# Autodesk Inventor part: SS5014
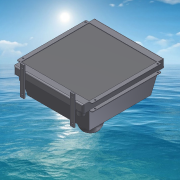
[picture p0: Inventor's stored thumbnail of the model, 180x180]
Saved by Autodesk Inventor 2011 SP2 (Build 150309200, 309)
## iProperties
Created: 2014-12
Part Number: SS5014
Document SubType Name: Modeling
Designer: Дорохин
Density: 0.416315 g/cm^3
Mass: 30000 g
Surface Area: 15790.2 cm^2
Volume: 72060.8 cm^3
Author: Дорохин
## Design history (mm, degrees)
sketch "Эскиз1"
  geometry: L1 (-275, 325)-(275, 325); L2 (300, 270)-(300, -270); L3 (275, -325)-(-275, -325); L4 (-300, -270)-(-300, 270); L5 (-295, 275)-(-275, 275); L6 (-275, 275)-(-275, 325); L7 (275, 325)-(275, 275); L8 (275, 275)-(295, 275); L9 (-295, -275)-(-275, -275); L10 (-275, -275)-(-275, -325); L11 (275, -325)-(275, -275); L12 (275, -275)-(295, -275); L13 (-295, 275)-(-300, 270); L14 (-300, -270)-(-295, -275); L15 (295, -275)-(300, -270); L16 (300, 270)-(295, 275); 5 further points
  constraints: 32 end point, 8 point on line, 6 perpendicular, 5 parallel, 1 horizontal
  dimensions: "d2" = 325 distance from line of point (0, 0) L1 (= 0.5 x d3); "d3" = 650 distance between parallel lines of L1 L3; "d4" = 0 distance between parallel lines of L5 L8; "d5" = 0 distance between parallel lines of L10 L6; "d6" = 0 distance between parallel lines of L12 L9; "d7" = 0 distance between parallel lines of L11 L7; "d8" = 25 distance between parallel lines of L6 L4 (= d10); "d9" = 550 distance between parallel lines of L7 L6; "d10" = 25 distance between parallel lines of L2 L7 (derived); "d11" = 50 distance between parallel lines of L8 L1 (= d13); "d12" = 550 distance between parallel lines of L12 L8; "d13" = 50 distance between parallel lines of L3 L12 (derived); "d14" = 300 distance from line of point (0, 0) L4 (= 0.5 x d15); "d15" = 600 distance between parallel lines of L2 L4; "d20" = 5 distance of L5.start point (-300, 275); "d21" = 5 distance of L4.end point (-300, 275) (= d20); "d22" = 5 distance of L4.start point (-300, -275) (= d20); "d23" = 5 distance of L9.start point (-300, -275) (= d22); "d24" = 5 distance of L12.end point (300, -275) (= d20); "d25" = 5 distance of L2.end point (300, -275) (= d24); "d26" = 5 distance of L2.start point (300, 275) (= d20); "d27" = 5 distance of L8.end point (300, 275) (= d26)
extrude "Выдавливание1" new body sketch "Эскиз1" distance "d28" = 63; taper "d29" = 0 deg
sketch "Эскиз2"
  geometry: L1 (-295, 275)-(-275, 275) reference; L2 (-300, -270)-(-300, 270) reference; L3 (-275, -275)-(-295, -275) reference; L4 (-289.5, 263.5)-(-285.5, 263.5); L5 (-285.5, 254.5)-(-289.5, 254.5); A1 r 4.5 centre (-289.5, 259) between (-289.5, 263.5) and (-289.5, 254.5); A2 r 4.5 centre (-285.5, 259) between (-285.5, 254.5) and (-285.5, 263.5); 1 further point
  constraints: 4 end point, 4 point on circle, 3 tangent, 2 centre point, 1 parallel
  dimensions: "d30" = 9 diameter of A1; "d31" = 9 diameter of A2; "d32" = 0 vertical distance of A2.centre A1.centre; "d33" = 4 distance of A2.centre A1.centre; "d34" = 16 distance from line of A2.centre L1; "d35" = 10.5 distance from line of A1.centre L2
extrude "Выдавливание2" cut sketch "Эскиз2" distance "d36" = 63; taper "d37" = 0 deg
pattern_linear "Прямоуг.массив1" dims "d40" = -498, "d43" = 575
sketch "Эскиз3"
  geometry: L1 (20, 63)-(0, 63) reference; L2 (0, 0)-(20, 0) reference; L3 (20, 0)-(20, 63) reference; L4 (20, 4)-(-5, 4); L5 (-5, 0)-(-5, 63) reference; L6 (-5, 4)-(-5, 59); L7 (-5, 59)-(20, 59); L8 (20, 0)-(20, 63) reference; L9 (20, 4)-(20, 59); L10 (570, 0)-(570, 63) reference; L11 (570, 4)-(595, 4); L12 (595, 0)-(595, 63) reference; L13 (595, 4)-(595, 59); L14 (595, 59)-(570, 59); L15 (570, 59)-(570, 4); L16 (570, 0)-(590, 0) reference; L17 (590, 63)-(570, 63) reference; 1 further point
  constraints: 16 end point, 8 point on line, 5 perpendicular, 1 collinear
  dimensions: "d44" = 4 distance between parallel lines of L4 L2; "d45" = 4 distance between parallel lines of L1 L7 (= d44); "d46" = 4 distance between parallel lines of L16 L11 (= d44); "d47" = 4 distance between parallel lines of L17 L14 (= d44)
extrude "Выдавливание3" cut sketch "Эскиз3" stored distance "d48" = 63; taper "d49" = 0 deg
sketch "Эскиз4"
  geometry: L1 (275, -325)-(-275, -325) reference; L2 (300, 270)-(300, -270) reference; L3 (-275, 325)-(275, 325) reference; L4 (-300, -270)-(-300, 270) reference; L5 (-275, 275)-(275, 275); L6 (275, 275)-(275, -275); L7 (275, -275)-(-275, -275); L8 (-275, -275)-(-275, 275); L9 (-270, 270)-(270, 270); L10 (270, 270)-(270, -270); L11 (270, -270)-(-270, -270); L12 (-270, -270)-(-270, 270); 1 further point
  constraints: 16 end point, 4 parallel, 2 horizontal, 2 perpendicular
  dimensions: "d50" = 550 distance between parallel lines of L6 L8; "d51" = 25 distance between parallel lines of L4 L8 (= d52); "d52" = 25 distance between parallel lines of L2 L6 (derived); "d53" = 550 distance of L5.end L6.end; "d54" = 50 distance between parallel lines of L1 L7 (= d55); "d55" = 50 distance between parallel lines of L3 L5 (derived); "d56" = 5 distance between parallel lines of L9 L5; "d57" = 5 distance between parallel lines of L8 L12; "d58" = 5 distance between parallel lines of L7 L11; "d59" = 5 distance between parallel lines of L10 L6
extrude "Выдавливание4" cut sketch "Эскиз4" distance "d60" = 4; taper "d61" = 0 deg
sketch "Эскиз5"
  geometry: L1 (-275, -325)-(-275, -275) reference; L2 (275, -275)-(275, -325) reference; L3 (-275, -325)-(275, -325) reference; L4 (-214.5, -325)-(-184.5, -325); L5 (-184.5, -325)-(-184.5, -335); L6 (-184.5, -335)-(-214.5, -335); L7 (-214.5, -335)-(-214.5, -325); L8 (184.5, -325)-(214.5, -325); L9 (214.5, -325)-(214.5, -335); L10 (214.5, -335)-(184.5, -335); L11 (184.5, -335)-(184.5, -325); 1 further point
  constraints: 16 end point, 4 parallel, 2 horizontal, 2 perpendicular, 2 point on line
  dimensions: "d62" = 369 distance between parallel lines of L11 L5; "d63" = 30 distance between parallel lines of L5 L7; "d64" = 30 distance between parallel lines of L9 L11; "d65" = 60.5 distance between parallel lines of L2 L9 (= d66); "d66" = 60.5 distance between parallel lines of L7 L1 (derived); "d67" = 0 distance between parallel lines of L10 L6; "d68" = 10 distance between parallel lines of L3 L6
extrude "Выдавливание5" join sketch "Эскиз5" distance "d69" = 50; taper "d71" = 0 deg; dims "d70" = 181, "d72" = 0
sketch "Эскиз6"
  geometry: L1 (30, 0)-(0, 0) reference; L2 (0, -231)-(30, -231) reference; L3 (30, -231)-(30, 0) reference; L4 (-399, -231)-(-399, 0) reference; 5 further points
  dimensions: "d73" = 0 horizontal distance of point (15, -206) point (15, -25); "d74" = 0 horizontal distance of point (-384, -206) point (-384, -25); "d75" = 0 vertical distance of point (15, -206) point (-384, -206); "d76" = 0 vertical distance of point (-384, -25) point (15, -25); "d77" = 181 distance of point (15, -206) point (15, -25); "d78" = 25 distance from line of point (15, -25) L1 (= d79); "d79" = 25 distance from line of L2 point (15, -206) (derived); "d80" = 399 distance of point (-384, -206) point (15, -206); "d81" = 15 distance from line of L3 point (15, -206) (= d82); "d82" = 15 distance from line of L4 point (-384, -206) (derived)
hole "Отверстие1" sketch "Эскиз6" at (15, -25), (-384, -25), (15, -206), (-384, -206) diameter "d83" = 14; stored, may be unused: countersink angle "d87" = 90 deg, drill point angle "d89" = 118 deg; dims "d84" = 6, "d85" = 4, "d86" = 2, "d88" = 10
sketch "Эскиз7"
  geometry: L1 (275, 325)-(275, 275) reference; L2 (-275, 325)-(275, 325) reference; L3 (-275, -325)-(-275, -275) reference; L4 (184.5, -325)-(-184.5, -325) reference; C1 r 25 at (237, 300); C2 r 25 at (-237, -300); C3 r 15 at (237, -300); 1 further point
  constraints: 3 centre point
  dimensions: "d90" = 600 vertical distance of C1.centre C2.centre; "d91" = 25 distance from line of L4 C2.centre (= d92); "d92" = 25 distance from line of C1.centre L2 (derived); "d93" = 38 distance from line of C2.centre L3; "d94" = 38 distance from line of C1.centre L1; "d95" = 50 diameter of C1; "d96" = 50 diameter of C2; "d99" = 0 vertical distance of C2.centre C3.centre; "d100" = 0 horizontal distance of C1.centre C3.centre; "d101" = 30 diameter of C3
extrude "Выдавливание6" join sketch "Эскиз7" distance "d97" = 30; taper "d98" = 0 deg
hole "Отверстие2" diameter "d104" = 38.952; stored, may be unused: countersink angle "d108" = 90 deg, drill point angle "d110" = 118 deg; dims "d102" = 10, "d103" = 10, "d105" = 25, "d106" = 43, "d107" = 2, "d109" = 40
hole "Отверстие3" diameter "d113" = 38.952; stored, may be unused: countersink angle "d117" = 90 deg, drill point angle "d119" = 118 deg; dims "d111" = 10, "d112" = 10, "d114" = 25, "d115" = 43, "d116" = 2, "d118" = 40
hole "Отверстие4" diameter "d122" = 18.631; stored, may be unused: countersink angle "d126" = 90 deg, drill point angle "d128" = 118 deg; dims "d120" = 10, "d121" = 10, "d123" = 20, "d124" = 22, "d125" = 2, "d127" = 40
sketch "Эскиз8"
  geometry: L1 (-275, 275)-(275, 275); L2 (275, 275)-(275, -275); L3 (275, -275)-(-275, -275); L4 (-275, -275)-(-275, 275); 1 further point
  constraints: 8 end point, 2 parallel, 1 horizontal, 1 perpendicular
extrude "Выдавливание7" join sketch "Эскиз8" distance "d129" = 167; taper "d130" = -10 deg
derived "Size 80 (0.55-0.75 кВт).ipt"
feature "Переместить тело1"
feature "Переместить тело2"
feature "Переместить тело3"
feature "Комбинировать1"
  node "Твердое тело2"
fillet "Сопряжение1" dims "d139" = 10
sketch "Эскиз10"
  geometry: L1 (482.553, 169.576)-(-8.553, 169.576) reference; L2 (512, 0)-(0, 0) reference; L3 (297, 24.788)-(177, 24.788); L4 (177, 24.788)-(177, 144.788); L5 (177, 144.788)-(297, 144.788); L6 (297, 144.788)-(297, 24.788); 1 further point
  constraints: 8 end point, 2 parallel, 1 horizontal, 1 perpendicular
  dimensions: "d140" = 120 distance of L5.end L3.start; "d141" = 120 distance of L3.start L3.end; "d142" = 24.78812 distance between parallel lines of L1 L5 (= d143); "d143" = 24.78812 distance between parallel lines of L2 L3 (derived); "d144" = 185.55339 distance from line of L1.start L6 (= d145); "d145" = 185.55339 distance from line of L1.end L4 (derived)
extrude "Выдавливание8" join sketch "Эскиз10" distance "d146" = 80; taper "d147" = 0 deg
chamfer "Фаска1" distance "d148" = 5; stored, may be unused: second distance "d149" = 2, angle "d150" = 45 deg
sketch "Эскиз11"
  geometry: L1 (-196.721, -288.08)-(-174.945, -288.08); L2 (-174.945, -288.08)-(-174.945, -308.018); L3 (-174.945, -308.018)-(-196.721, -308.018); L4 (-196.721, -308.018)-(-196.721, -288.08); L5 (151.858, -293.922)-(214.19, -293.922); L6 (214.19, -293.922)-(214.19, -303.891); L7 (214.19, -303.891)-(151.858, -303.891); L8 (151.858, -303.891)-(151.858, -293.922); L9 (150.85, 302.479)-(198.34, 302.479); L10 (198.34, 302.479)-(198.34, 282.54); L11 (198.34, 282.54)-(150.85, 282.54); L12 (150.85, 282.54)-(150.85, 302.479); 1 further point
  constraints: 6 other
extrude "Выдавливание9" join sketch "Эскиз11" distance "d151" = 2; taper "d152" = 0 deg
node "Твердое тело1"
feature "NONE::Size 80 (0.55-0.75 кВт).ipt" dims "d131" = 10
tag "Элемент создания маркировки1"
other parameters: "d132" = 270 deg, "d133" = 270 deg, "d135" = 0, "d136" = -247
